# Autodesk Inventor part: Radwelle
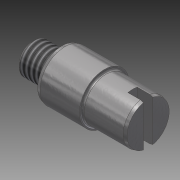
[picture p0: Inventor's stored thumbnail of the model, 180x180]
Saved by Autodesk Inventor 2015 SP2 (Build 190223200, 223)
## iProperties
Created: 2012-07
Part Number: Radwelle
Material: Stahl, galvanisiert
Document SubType Name: Modeling
Designer: rYan
Density: 7.85 g/cm^3
Mass: 5.08301 g
Surface Area: 5.04315 cm^2
Volume: 0.647518 cm^3
Appearance: Galvanisiert
Author: rYan
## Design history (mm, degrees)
revolve "Umdrehung1" stored, may be unused: angle "d7" = 90 deg
sketch "Skizze2"
  geometry: L1 (-3.5, -0.75)-(3.5, -0.75); L2 (3.5, -0.75)-(3.5, 0.75); L3 (3.5, 0.75)-(-3.5, 0.75); L4 (-3.5, 0.75)-(-3.5, -0.75); L5 (-3.5, -0.75)-(3.5, 0.75); L6 (3.5, -0.75)-(-3.5, 0.75); C1 r 3.5 at (0, 0) reference; C2 r 3.5 at (0, 0) reference
  constraints: 12 end point, 2 midpoint, 2 parallel, 1 horizontal, 1 perpendicular
  dimensions: "d24" = 7 distance of L3.end L2.end; "d25" = 1.5 distance of L2.end L1.end
extrude "Extrusion1" cut sketch "Skizze2" distance "d9" = 2.5; taper "d10" = 0 deg
feature "Gewinde1" dims "d11" = 3.5, "d12" = 0
chamfer "Fase1" distance "d13" = 0.5; stored, may be unused: second distance "d14" = 2, angle "d15" = 15 deg
chamfer "Fase2" distance "d16" = 0.5; stored, may be unused: second distance "d17" = 2, angle "d18" = 45 deg
chamfer "Fase3" distance "d21" = 0.5; stored, may be unused: second distance "d22" = 2, angle "d23" = 15 deg
fillet "Rundung1" dims "d26" = 0.3
node "Volumenkörper1"
sketch "Skizze1"
  geometry: L1 (0, 0)-(0, 2.5); L2 (0, 2.5)-(4.8, 2.5); L3 (4.8, 2.5)-(4.8, 4); L4 (4.8, 4)-(11.6, 4); L5 (18.6, 3.5)-(18.6, 0); L6 (18.6, 0)-(0, 0); L7 (11.6, 4)-(11.6, 3.5); L8 (11.6, 3.5)-(18.6, 3.5); L9 (18.6, 3.5)-(18.6, 0)
  constraints: 18 end point, 4 parallel, 3 perpendicular, 1 collinear, 1 vertical
  dimensions: "d0" = 18.6 distance between parallel lines of L5 L1; "d2" = 5 diameter of L2 L6; "d3" = 8 diameter of L4 L6; "d4" = 4.8 distance between parallel lines of L1 L3; "d19" = 7 diameter of L8 L6; "d20" = 7 distance between parallel lines of L5 L7
node "Projizierte Kontur1"
